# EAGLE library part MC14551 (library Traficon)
Quad 2?Channel Analog Multiplexer/Demultiplexer
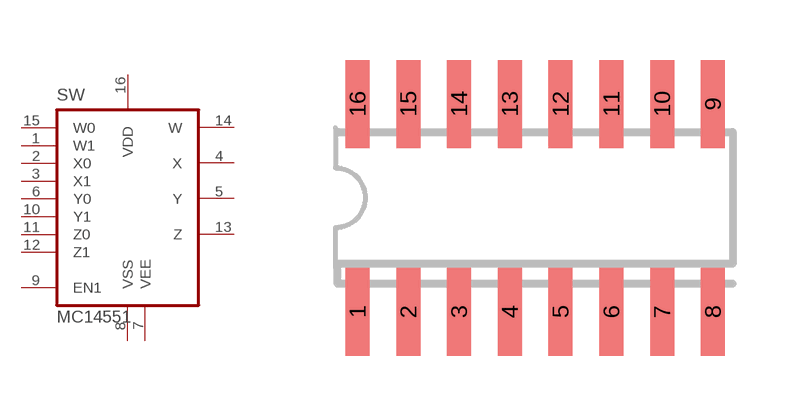
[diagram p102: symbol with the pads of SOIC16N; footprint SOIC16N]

Designator prefix SW

## MC14551  [SOIC16N]
1  W1
2  X0
3  X1
4  X
5  Y
6  Y0
7  VEE
8  VSS
9  EN1
10  Y1
11  Z0
12  Z1
13  Z
14  W
15  W0
16  VDD

## Footprint SOIC16N (pad centres in mm)
SMALL OUTLINE INTEGRATED CIRCUIT
smd 0.6 x 2.2: 1 -4.445,-2.6; 2 -3.175,-2.6; 3 -1.905,-2.6; 4 -0.635,-2.6; 5 0.635,-2.6; 6 1.905,-2.6; 7 3.175,-2.6; 8 4.445,-2.6; 9 4.445,2.6; 10 3.175,2.6; 11 1.905,2.6; 12 0.635,2.6; 13 -0.635,2.6; 14 -1.905,2.6; 15 -3.175,2.6; 16 -4.445,2.6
